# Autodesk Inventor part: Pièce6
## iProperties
Shininess: 64.0
Length Units: 11269
Angle Units: 11279
Time Units: 11290
Mass Units: 11283
Length Display Precision: 3
Angle Display Precision: 2
Compacted: True
Part Number: Pièce6
Document SubType Name: Modeling
Created: 2004-06
Material: Par défaut
Designer: laurent
Density: 0.0
Volumn: 0.0
Area: 0.0
PropertySet Name: Model Information
Control State: 0
Master: False
Checked Out: False
Author: laurent
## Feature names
1. Extrusion1
2. Balayage2
3. Balayage3
4. Révolution1 [Revolution]
5. Extrusion2
6. Extrusion3
7. Extrusion4
8. Balayage6
9. Balayage7
10. Réseau rectangulaire2 [Rectangular Pattern]
